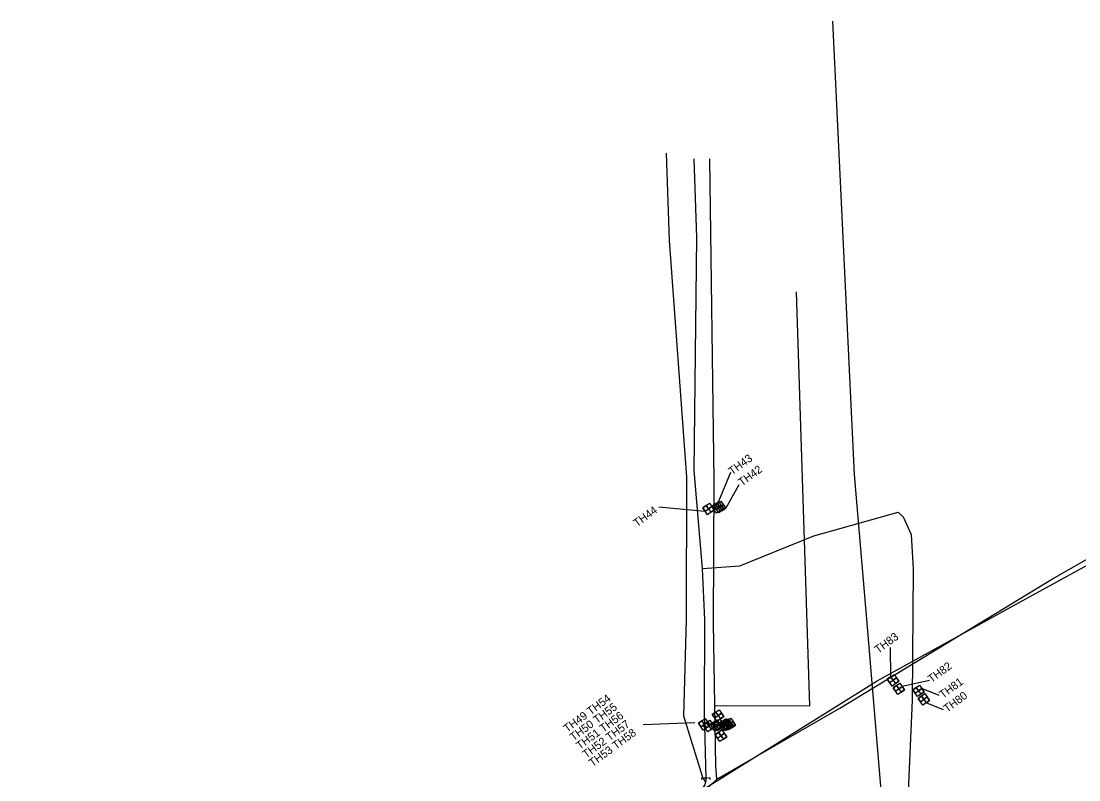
# Model space of a CAD drawing. Extents: x 507915 to 518914, y 880723 to 883087.
# Drawn here: x 508941.8 to 509259.1, y 882330.6 to 882558.4 of the extents above; entities that cross this region are included whole.
import ezdxf

# ---------------------------------------------------------------- set-up
doc = ezdxf.new("R2010")
doc.units = 0
for name, color, linetype in [('ConduitDB', 7, 'Continuous'), ('ConduitOT', 7, 'Continuous'), ('ConstLines', 7, 'Continuous'), ('GuardrailLt_ep', 7, 'Continuous'), ('GuardrailRt_ep', 7, 'Continuous'), ('Luminaire', 7, 'Continuous'), ('Miscellaneous2', 7, 'Continuous'), ('Miscellaneous3', 7, 'Continuous'), ('PavtAsphalt_ep', 7, 'Continuous'), ('PMBikeLane_ep', 7, 'Continuous')]:
    doc.layers.add(name, color=color, linetype=linetype)

msp = doc.modelspace()

# ---------------------------------------------------------------- linework, layer by layer
at = {"layer": 'ConduitDB'}
msp.add_lwpolyline([(509149.91, 882352.99), (509178.34, 882352.86), (509174.43, 882477.17)], dxfattribs=at)
at = {"layer": 'ConduitOT'}
for p, q in [((509136.29, 882492.59), (509135.37, 882518.78)), ((509144.5, 882493.5), (509143.65, 882517.02))]:
    msp.add_line(p, q, dxfattribs=at)
at = {"layer": 'ConstLines'}
for points in [[(509150.52, 882330.83), (509187.35, 882352.15), (509251.15, 882390.97), (509283.1, 882409.2), (509313.1, 882425.71), (509333.68, 882437.65), (509381.11, 882463), (509511.48, 882517.48)], [(509091.54, 882291.51), (509094.58, 882293.28), (509143.11, 882323.78), (509150.52, 882330.83), (509150.2, 882334.84), (509149.51, 882377.66), (509149.68, 882420.56), (509148.41, 882517.05)]]:
    msp.add_lwpolyline(points, dxfattribs=at)
at = {"layer": 'GuardrailRt_ep'}
for p, q in [((509154.54, 882422.88), (509151.01, 882414.17)), ((509157.13, 882419.24), (509153.14, 882412.23)), ((509133.13, 882412.55), (509146.97, 882411.26)), ((509202.47, 882370.4), (509202.62, 882361.58)), ((509214.33, 882360.45), (509206.1, 882358.69)), ((509217.17, 882355.99), (509212.01, 882358.09)), ((509218.48, 882351.7), (509213.31, 882353.79)), ((509128.37, 882347.25), (509143.85, 882347.9))]:
    msp.add_line(p, q, dxfattribs=at)
at = {"layer": 'Luminaire'}
msp.add_lwpolyline([(509209.54, 882030.61), (509208.49, 882117.66), (509208.13, 882156.35), (509208.41, 882184.48), (509208.19, 882227.96), (509206.41, 882248.67), (509195.56, 882377.68), (509191.83, 882422.32), (509185.31, 882558.4)], dxfattribs=at)
at = {"layer": 'Miscellaneous2'}
for p, q in [((509145.96, 882331.23), (509146.46, 882331.23)), ((509145.96, 882330.73), (509145.96, 882331.23)), ((509146.71, 882331.23), (509147.71, 882331.23)), ((509147.96, 882331.23), (509148.46, 882331.23)), ((509148.46, 882330.73), (509148.46, 882331.23))]:
    msp.add_line(p, q, dxfattribs=at)
at = {"layer": 'Miscellaneous3'}
msp.add_lwpolyline([(508882.11, 882139.28), (508990.02, 882214.29), (509029.72, 882243.96), (509087.02, 882285.78), (509130.99, 882317.86), (509136.55, 882321.71), (509138.14, 882323.57), (509145.35, 882327.1), (509198.61, 882360.32), (509243.19, 882384.95), (509308.25, 882420.73), (509348.67, 882443.03), (509435.21, 882484.91)], dxfattribs=at)
at = {"layer": 'PavtAsphalt_ep'}
for points in [[(508946.27, 882182.61), (508990.71, 882213.97), (509030.15, 882243.24), (509087.3, 882285.27), (509131.16, 882317.05), (509145.15, 882325.32), (509146.91, 882329.08), (509147.21, 882329.98), (509147.25, 882330.89), (509146.76, 882351.04), (509146.84, 882378.71), (509146.15, 882394.1), (509143.64, 882423.51), (509144.5, 882493.5)], [(508946.38, 882183.08), (508990.55, 882214.25), (509029.91, 882243.66), (509087.28, 882285.5), (509130.89, 882317.31), (509144.84, 882325.87), (509146.91, 882329.08), (509147.21, 882329.98), (509146.27, 882331.32), (509140.54, 882349.76), (509141.42, 882378.79), (509141.44, 882421.55), (509136.29, 882492.59)], [(509146.15, 882394.1), (509157.35, 882394.86), (509179.56, 882403.85), (509204.9, 882411.03)], [(509213.58, 882113.61), (509213.17, 882115.68), (509214.27, 882140.38), (509214.05, 882192.03), (509209.45, 882233.65), (509207.93, 882245.59), (509208.55, 882252.33), (509212.63, 882254.27), (509211.35, 882255.03), (509205.24, 882265.33), (509209.21, 882354.52), (509209.44, 882393.98), (509208.91, 882404.22), (509206.52, 882409.46), (509204.9, 882411.03)]]:
    msp.add_lwpolyline(points, dxfattribs=at)
at = {"layer": 'PMBikeLane_ep'}
for p, q in [((509146.24, 882412.28), (509148.29, 882413.72)), ((509147.27, 882413), (509146.24, 882412.28)), ((509146.97, 882411.26), (509149.01, 882412.7)), ((509147.27, 882413), (509148.71, 882410.96)), ((509147.99, 882411.98), (509147.27, 882413)), ((509149.01, 882412.7), (509147.99, 882411.98)), ((509148.29, 882413.72), (509149.73, 882411.68)), ((509148.97, 882412.73), (509151.01, 882414.17)), ((509149.99, 882413.45), (509148.97, 882412.73)), ((509150.41, 882410.68), (509148.97, 882412.73)), ((509148.97, 882412.73), (509149.69, 882411.7)), ((509149.73, 882411.68), (509149.01, 882412.7)), ((509149.65, 882412.83), (509151.7, 882414.27)), ((509150.68, 882413.55), (509149.65, 882412.83)), ((509151.1, 882410.79), (509149.65, 882412.83)), ((509149.65, 882412.83), (509150.38, 882411.81)), ((509149.69, 882411.7), (509151.73, 882413.15)), ((509149.69, 882411.7), (509150.71, 882412.43)), ((509149.99, 882413.45), (509151.43, 882411.4)), ((509150.71, 882412.43), (509149.99, 882413.45)), ((509150.38, 882411.81), (509152.42, 882413.25)), ((509150.38, 882411.81), (509151.4, 882412.53)), ((509150.68, 882413.55), (509152.12, 882411.51)), ((509151.4, 882412.53), (509150.68, 882413.55)), ((509151.73, 882413.15), (509150.71, 882412.43)), ((509150.71, 882412.43), (509151.43, 882411.4)), ((509150.71, 882412.43), (509150.71, 882412.43)), ((509151.01, 882414.17), (509152.45, 882412.13)), ((509152.42, 882413.25), (509151.4, 882412.53)), ((509151.4, 882412.53), (509152.12, 882411.51)), ((509151.4, 882412.53), (509151.4, 882412.53)), ((509151.7, 882414.27), (509153.14, 882412.23)), ((509152.45, 882412.13), (509151.73, 882413.15)), ((509153.14, 882412.23), (509152.42, 882413.25)), ((509147.69, 882410.24), (509146.24, 882412.28)), ((509146.24, 882412.28), (509146.97, 882411.26)), ((509146.97, 882411.26), (509147.99, 882411.98)), ((509149.73, 882411.68), (509147.69, 882410.24)), ((509147.99, 882411.98), (509148.71, 882410.96)), ((509147.99, 882411.98), (509147.99, 882411.98)), ((509148.71, 882410.96), (509149.73, 882411.68)), ((509152.45, 882412.13), (509150.41, 882410.68)), ((509153.14, 882412.23), (509151.1, 882410.79)), ((509151.43, 882411.4), (509152.45, 882412.13)), ((509152.12, 882411.51), (509153.14, 882412.23)), ((509201.6, 882360.85), (509203.65, 882362.3)), ((509203.65, 882362.3), (509205.09, 882360.25)), ((509202.62, 882361.58), (509201.6, 882360.85)), ((509203.05, 882358.81), (509201.6, 882360.85)), ((509201.6, 882360.85), (509202.32, 882359.83)), ((509202.32, 882359.83), (509204.37, 882361.28)), ((509202.32, 882359.83), (509203.35, 882360.55)), ((509202.62, 882361.58), (509204.07, 882359.53)), ((509203.35, 882360.55), (509202.62, 882361.58)), ((509205.09, 882360.25), (509203.05, 882358.81)), ((509203.34, 882358.27), (509205.38, 882359.71)), ((509204.36, 882358.99), (509203.34, 882358.27)), ((509204.37, 882361.28), (509203.35, 882360.55)), ((509203.35, 882360.55), (509204.07, 882359.53)), ((509203.35, 882360.55), (509203.35, 882360.55)), ((509204.06, 882357.25), (509206.1, 882358.69)), ((509204.07, 882359.53), (509205.09, 882360.25)), ((509204.36, 882358.99), (509205.8, 882356.95)), ((509205.08, 882357.97), (509204.36, 882358.99)), ((509205.09, 882360.25), (509204.37, 882361.28)), ((509206.1, 882358.69), (509205.08, 882357.97)), ((509205.38, 882359.71), (509206.82, 882357.67)), ((509206.82, 882357.67), (509206.1, 882358.69)), ((509209.24, 882357.67), (509211.28, 882359.11)), ((509211.28, 882359.11), (509212.73, 882357.07)), ((509204.78, 882356.23), (509203.34, 882358.27)), ((509203.34, 882358.27), (509204.06, 882357.25)), ((509204.06, 882357.25), (509205.08, 882357.97)), ((509206.82, 882357.67), (509204.78, 882356.23)), ((509205.08, 882357.97), (509205.8, 882356.95)), ((509205.08, 882357.97), (509205.08, 882357.97)), ((509205.8, 882356.95), (509206.82, 882357.67)), ((509210.26, 882358.39), (509209.24, 882357.67)), ((509210.68, 882355.62), (509209.24, 882357.67)), ((509209.24, 882357.67), (509209.96, 882356.65)), ((509209.96, 882356.65), (509212.01, 882358.09)), ((509209.96, 882356.65), (509210.98, 882357.37)), ((509210.26, 882358.39), (509211.71, 882356.35)), ((509210.98, 882357.37), (509210.26, 882358.39)), ((509212.73, 882357.07), (509210.68, 882355.62)), ((509210.84, 882355.11), (509212.89, 882356.55)), ((509211.86, 882355.83), (509210.84, 882355.11)), ((509212.01, 882358.09), (509210.98, 882357.37)), ((509210.98, 882357.37), (509211.71, 882356.35)), ((509210.98, 882357.37), (509210.98, 882357.37)), ((509211.56, 882354.09), (509213.61, 882355.53)), ((509211.71, 882356.35), (509212.73, 882357.07)), ((509211.86, 882355.83), (509213.31, 882353.79)), ((509212.59, 882354.81), (509211.86, 882355.83)), ((509212.73, 882357.07), (509212.01, 882358.09)), ((509213.61, 882355.53), (509212.59, 882354.81)), ((509212.89, 882356.55), (509214.33, 882354.51)), ((509214.33, 882354.51), (509213.61, 882355.53)), ((509212.29, 882353.07), (509210.84, 882355.11)), ((509210.84, 882355.11), (509211.56, 882354.09)), ((509211.56, 882354.09), (509212.59, 882354.81)), ((509214.33, 882354.51), (509212.29, 882353.07)), ((509212.59, 882354.81), (509213.31, 882353.79)), ((509212.59, 882354.81), (509212.59, 882354.81)), ((509213.31, 882353.79), (509214.33, 882354.51)), ((509144.96, 882347.61), (509147, 882349.05)), ((509147, 882349.05), (509148.44, 882347.01)), ((509149.11, 882350.26), (509151.16, 882351.7)), ((509150.14, 882350.98), (509149.11, 882350.26)), ((509150.56, 882348.22), (509149.11, 882350.26)), ((509149.11, 882350.26), (509149.84, 882349.24)), ((509149.84, 882349.24), (509151.88, 882350.68)), ((509149.84, 882349.24), (509150.86, 882349.96)), ((509150.14, 882350.98), (509151.58, 882348.94)), ((509150.86, 882349.96), (509150.14, 882350.98)), ((509152.6, 882349.66), (509150.56, 882348.22)), ((509151.88, 882350.68), (509150.86, 882349.96)), ((509150.86, 882349.96), (509151.58, 882348.94)), ((509150.86, 882349.96), (509150.86, 882349.96)), ((509151.16, 882351.7), (509152.6, 882349.66)), ((509151.58, 882348.94), (509152.6, 882349.66)), ((509152.6, 882349.66), (509151.88, 882350.68)), ((509151.93, 882347.54), (509153.97, 882348.99)), ((509152.62, 882347.7), (509154.66, 882349.14)), ((509153.97, 882348.99), (509155.41, 882346.94)), ((509154.66, 882349.14), (509156.1, 882347.1)), ((509145.98, 882348.33), (509144.96, 882347.61)), ((509146.4, 882345.57), (509144.96, 882347.61)), ((509144.96, 882347.61), (509145.68, 882346.59)), ((509145.68, 882346.59), (509147.72, 882348.03)), ((509145.68, 882346.59), (509146.7, 882347.31)), ((509145.98, 882348.33), (509147.42, 882346.29)), ((509146.7, 882347.31), (509145.98, 882348.33)), ((509146.34, 882347.07), (509148.38, 882348.51)), ((509147.36, 882347.79), (509146.34, 882347.07)), ((509147.78, 882345.03), (509146.34, 882347.07)), ((509146.34, 882347.07), (509147.06, 882346.05)), ((509148.44, 882347.01), (509146.4, 882345.57)), ((509147.72, 882348.03), (509146.7, 882347.31)), ((509146.7, 882347.31), (509147.42, 882346.29)), ((509146.7, 882347.31), (509146.7, 882347.31)), ((509147.06, 882346.05), (509149.1, 882347.49)), ((509147.06, 882346.05), (509148.08, 882346.77)), ((509147.36, 882347.79), (509148.8, 882345.75)), ((509148.08, 882346.77), (509147.36, 882347.79)), ((509147.42, 882346.29), (509148.44, 882347.01)), ((509148.44, 882347.01), (509147.72, 882348.03)), ((509149.82, 882346.47), (509147.78, 882345.03)), ((509149.1, 882347.49), (509148.08, 882346.77)), ((509148.08, 882346.77), (509148.8, 882345.75)), ((509148.08, 882346.77), (509148.08, 882346.77)), ((509148.38, 882348.51), (509149.82, 882346.47)), ((509148.48, 882347.25), (509150.52, 882348.69)), ((509149.5, 882347.97), (509148.48, 882347.25)), ((509149.92, 882345.21), (509148.48, 882347.25)), ((509148.48, 882347.25), (509149.2, 882346.23)), ((509148.8, 882345.75), (509149.82, 882346.47)), ((509149.82, 882346.47), (509149.1, 882347.49)), ((509149.2, 882346.23), (509151.24, 882347.67)), ((509149.2, 882346.23), (509150.22, 882346.95)), ((509149.29, 882347.39), (509151.34, 882348.84)), ((509150.32, 882348.12), (509149.29, 882347.39)), ((509150.74, 882345.35), (509149.29, 882347.39)), ((509149.29, 882347.39), (509150.02, 882346.37)), ((509149.5, 882347.97), (509150.94, 882345.93)), ((509150.22, 882346.95), (509149.5, 882347.97)), ((509151.96, 882346.65), (509149.92, 882345.21)), ((509150.02, 882346.37), (509152.06, 882347.82)), ((509150.02, 882346.37), (509151.04, 882347.09)), ((509151.24, 882347.67), (509150.22, 882346.95)), ((509150.22, 882346.95), (509150.94, 882345.93)), ((509150.22, 882346.95), (509150.22, 882346.95)), ((509150.32, 882348.12), (509151.76, 882346.07)), ((509151.04, 882347.09), (509150.32, 882348.12)), ((509150.52, 882348.69), (509151.96, 882346.65)), ((509152.78, 882346.79), (509150.74, 882345.35)), ((509150.94, 882345.93), (509151.96, 882346.65)), ((509151.02, 882347.5), (509153.06, 882348.94)), ((509152.04, 882348.22), (509151.02, 882347.5)), ((509152.46, 882345.46), (509151.02, 882347.5)), ((509151.02, 882347.5), (509151.74, 882346.48)), ((509152.06, 882347.82), (509151.04, 882347.09)), ((509151.04, 882347.09), (509151.76, 882346.07)), ((509151.04, 882347.09), (509151.04, 882347.09)), ((509151.96, 882346.65), (509151.24, 882347.67)), ((509151.34, 882348.84), (509152.78, 882346.79)), ((509151.66, 882347.51), (509153.7, 882348.95)), ((509152.68, 882348.23), (509151.66, 882347.51)), ((509153.1, 882345.47), (509151.66, 882347.51)), ((509151.66, 882347.51), (509152.38, 882346.49)), ((509151.74, 882346.48), (509153.78, 882347.92)), ((509151.74, 882346.48), (509152.76, 882347.2)), ((509151.76, 882346.07), (509152.78, 882346.79)), ((509152.95, 882348.27), (509151.93, 882347.54)), ((509153.37, 882345.5), (509151.93, 882347.54)), ((509151.93, 882347.54), (509152.65, 882346.52)), ((509152.04, 882348.22), (509153.48, 882346.18)), ((509152.76, 882347.2), (509152.04, 882348.22)), ((509152.78, 882346.79), (509152.06, 882347.82)), ((509152.38, 882346.49), (509154.42, 882347.93)), ((509152.38, 882346.49), (509153.4, 882347.21)), ((509154.5, 882346.9), (509152.46, 882345.46)), ((509153.64, 882348.42), (509152.62, 882347.7)), ((509154.06, 882345.66), (509152.62, 882347.7)), ((509152.62, 882347.7), (509153.34, 882346.68)), ((509152.65, 882346.52), (509154.69, 882347.97)), ((509152.65, 882346.52), (509153.67, 882347.24)), ((509152.68, 882348.23), (509154.12, 882346.19)), ((509153.4, 882347.21), (509152.68, 882348.23)), ((509153.78, 882347.92), (509152.76, 882347.2)), ((509152.76, 882347.2), (509153.48, 882346.18)), ((509152.76, 882347.2), (509152.76, 882347.2)), ((509152.95, 882348.27), (509154.39, 882346.22)), ((509153.67, 882347.24), (509152.95, 882348.27)), ((509153.06, 882348.94), (509154.5, 882346.9)), ((509155.14, 882346.91), (509153.1, 882345.47)), ((509153.34, 882346.68), (509155.38, 882348.12)), ((509153.34, 882346.68), (509154.36, 882347.4)), ((509155.41, 882346.94), (509153.37, 882345.5)), ((509154.42, 882347.93), (509153.4, 882347.21)), ((509153.4, 882347.21), (509154.12, 882346.19)), ((509153.4, 882347.21), (509153.4, 882347.21)), ((509153.48, 882346.18), (509154.5, 882346.9)), ((509153.64, 882348.42), (509155.08, 882346.38)), ((509154.36, 882347.4), (509153.64, 882348.42)), ((509154.69, 882347.97), (509153.67, 882347.24)), ((509153.67, 882347.24), (509154.39, 882346.22)), ((509153.67, 882347.24), (509153.67, 882347.24)), ((509153.7, 882348.95), (509155.14, 882346.91)), ((509154.5, 882346.9), (509153.78, 882347.92)), ((509156.1, 882347.1), (509154.06, 882345.66)), ((509154.12, 882346.19), (509155.14, 882346.91)), ((509155.38, 882348.12), (509154.36, 882347.4)), ((509154.36, 882347.4), (509155.08, 882346.38)), ((509154.36, 882347.4), (509154.36, 882347.4)), ((509154.39, 882346.22), (509155.41, 882346.94)), ((509155.14, 882346.91), (509154.42, 882347.93)), ((509155.41, 882346.94), (509154.69, 882347.97)), ((509155.08, 882346.38), (509156.1, 882347.1)), ((509156.1, 882347.1), (509155.38, 882348.12)), ((509149.99, 882344.2), (509152.03, 882345.64)), ((509151.01, 882344.92), (509149.99, 882344.2)), ((509151.43, 882342.16), (509149.99, 882344.2)), ((509149.99, 882344.2), (509150.71, 882343.18)), ((509150.71, 882343.18), (509152.75, 882344.62)), ((509150.71, 882343.18), (509151.73, 882343.9)), ((509151.01, 882344.92), (509152.45, 882342.88)), ((509151.73, 882343.9), (509151.01, 882344.92)), ((509153.47, 882343.6), (509151.43, 882342.16)), ((509152.75, 882344.62), (509151.73, 882343.9)), ((509151.73, 882343.9), (509152.45, 882342.88)), ((509151.73, 882343.9), (509151.73, 882343.9)), ((509152.03, 882345.64), (509153.47, 882343.6)), ((509152.45, 882342.88), (509153.47, 882343.6)), ((509153.47, 882343.6), (509152.75, 882344.62))]:
    msp.add_line(p, q, dxfattribs=at)

# ---------------------------------------------------------------- texts
at = {"layer": 'GuardrailLt_ep'}
for s, p in [('TH43', (509155.08, 882422.01)), ('TH42', (509158.02, 882418.69)), ('TH44', (509126.55, 882406.43)), ('TH83', (509198.91, 882368.47)), ('TH82', (509214.89, 882359.64)), ('TH81', (509218.33, 882354.93)), ('TH49 TH54', (509105.59, 882344.76)), ('TH80', (509219.59, 882350.76)), ('TH50 TH55', (509107.49, 882342.18)), ('TH51 TH56', (509109.39, 882339.6)), ('TH52 TH57', (509111.29, 882337.02)), ('TH53 TH58', (509113.2, 882334.44))]:
    msp.add_text(s, height=2.4, rotation=36.4175, dxfattribs=at).set_placement(p)

doc.saveas('drawing.dxf')
